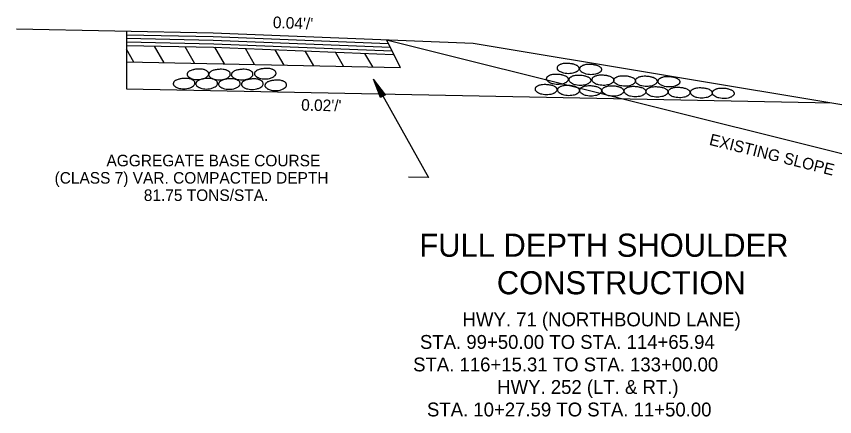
# Model space of a CAD drawing. Extents: x 634177 to 635904, y 289936 to 290970.
# Drawn here: x 635711.28 to 635753.77, y 290762.35 to 290783.15 of the extents above; entities that cross this region are included whole.
import ezdxf

# ---------------------------------------------------------------- set-up
doc = ezdxf.new("R2010")
doc.units = 0
doc.layers.add('Default', color=7, linetype='Continuous')

msp = doc.modelspace()

# ---------------------------------------------------------------- linework, layer by layer
at = {"layer": 'Default'}
for p, q in [((635711.282, 290782.495), (635721.496, 290782.291)), ((635716.996, 290782.375), (635716.996, 290779.379)), ((635716.996, 290782.006), (635721.496, 290781.916)), ((635717, 290782.194), (635721.496, 290782.104)), ((635721.496, 290782.291), (635734.996, 290781.751)), ((635721.496, 290782.104), (635730.592, 290781.74)), ((635716.996, 290781.816), (635721.531, 290781.72)), ((635716.996, 290781.63), (635721.511, 290781.541)), ((635718.959, 290780.739), (635718.462, 290781.601)), ((635720.536, 290780.707), (635720.039, 290781.57)), ((635721.496, 290781.916), (635730.687, 290781.548)), ((635721.531, 290781.72), (635730.787, 290781.35)), ((635730.496, 290781.931), (635731.215, 290780.493)), ((635730.496, 290781.931), (635762.121, 290774.026)), ((635734.996, 290781.751), (635784.496, 290773.501)), ((635717.382, 290780.771), (635716.996, 290781.439)), ((635721.511, 290781.541), (635730.854, 290781.167)), ((635722.087, 290780.676), (635721.589, 290781.539)), ((635723.654, 290780.645), (635723.175, 290781.474)), ((635725.185, 290780.614), (635724.724, 290781.412)), ((635726.726, 290780.583), (635726.283, 290781.35)), ((635728.274, 290780.552), (635727.85, 290781.287)), ((635729.787, 290780.522), (635729.38, 290781.226)), ((635716.996, 290780.778), (635731.215, 290780.493)), ((635730.459, 290779.075), (635729.827, 290779.88)), ((635730.195, 290778.925), (635729.827, 290779.88)), ((635730.437, 290779.062), (635729.911, 290779.733)), ((635730.217, 290778.937), (635729.911, 290779.733)), ((635730.24, 290778.95), (635729.997, 290779.582)), ((635730.415, 290779.05), (635729.997, 290779.582)), ((635716.996, 290779.379), (635753.626, 290778.646)), ((635730.393, 290779.037), (635730.08, 290779.435)), ((635730.262, 290778.963), (635730.08, 290779.435)), ((635730.284, 290778.975), (635730.165, 290779.286)), ((635730.37, 290779.024), (635730.165, 290779.286)), ((635730.459, 290779.075), (635730.195, 290778.925)), ((635730.306, 290778.988), (635730.248, 290779.139)), ((635730.348, 290779.012), (635730.248, 290779.139))]:
    msp.add_line(p, q, dxfattribs=at)
msp.add_lwpolyline([(635729.827, 290779.88), (635732.687, 290774.784), (635731.642, 290774.787)], dxfattribs=at)
for points in [[(635740.458, 290780.546), (635740.48, 290780.507), (635740.492, 290780.474), (635740.501, 290780.429), (635740.494, 290780.402), (635740.471, 290780.359), (635740.444, 290780.325), (635740.397, 290780.289), (635740.366, 290780.262), (635740.339, 290780.253), (635740.28, 290780.224), (635740.179, 290780.197), (635740.026, 290780.172), (635739.871, 290780.174), (635739.706, 290780.201), (635739.542, 290780.26), (635739.448, 290780.325), (635739.389, 290780.395), (635739.376, 290780.451), (635739.378, 290780.503), (635739.396, 290780.557), (635739.416, 290780.582), (635739.448, 290780.609), (635739.488, 290780.631), (635739.535, 290780.66), (635739.574, 290780.674), (635739.648, 290780.699), (635739.754, 290780.714), (635739.898, 290780.719), (635740.003, 290780.71), (635740.111, 290780.696), (635740.168, 290780.683), (635740.244, 290780.665), (635740.332, 290780.631), (635740.381, 290780.604), (635740.442, 290780.559), (635740.469, 290780.534)], [(635720.186, 290780.237), (635720.164, 290780.199), (635720.152, 290780.165), (635720.143, 290780.12), (635720.15, 290780.093), (635720.173, 290780.05), (635720.2, 290780.017), (635720.247, 290779.981), (635720.278, 290779.954), (635720.305, 290779.945), (635720.364, 290779.915), (635720.465, 290779.888), (635720.618, 290779.864), (635720.773, 290779.866), (635720.938, 290779.893), (635721.102, 290779.951), (635721.196, 290780.017), (635721.255, 290780.086), (635721.268, 290780.143), (635721.266, 290780.194), (635721.248, 290780.248), (635721.228, 290780.273), (635721.196, 290780.3), (635721.156, 290780.323), (635721.109, 290780.352), (635721.07, 290780.365), (635720.996, 290780.39), (635720.89, 290780.406), (635720.746, 290780.41), (635720.641, 290780.401), (635720.533, 290780.388), (635720.476, 290780.374), (635720.4, 290780.356), (635720.312, 290780.323), (635720.263, 290780.296), (635720.202, 290780.251), (635720.175, 290780.226)], [(635721.309, 290780.224), (635721.287, 290780.185), (635721.276, 290780.152), (635721.267, 290780.107), (635721.273, 290780.08), (635721.296, 290780.037), (635721.323, 290780.003), (635721.37, 290779.967), (635721.402, 290779.94), (635721.429, 290779.931), (635721.487, 290779.902), (635721.588, 290779.875), (635721.741, 290779.85), (635721.897, 290779.852), (635722.061, 290779.879), (635722.225, 290779.938), (635722.32, 290780.003), (635722.378, 290780.073), (635722.392, 290780.129), (635722.389, 290780.181), (635722.371, 290780.235), (635722.351, 290780.26), (635722.32, 290780.287), (635722.279, 290780.309), (635722.232, 290780.338), (635722.194, 290780.352), (635722.119, 290780.377), (635722.014, 290780.392), (635721.87, 290780.397), (635721.764, 290780.388), (635721.656, 290780.374), (635721.6, 290780.361), (635721.523, 290780.343), (635721.435, 290780.309), (635721.386, 290780.282), (635721.325, 290780.237), (635721.298, 290780.212)], [(635722.486, 290780.223), (635722.464, 290780.185), (635722.453, 290780.151), (635722.444, 290780.106), (635722.45, 290780.079), (635722.473, 290780.037), (635722.5, 290780.003), (635722.547, 290779.967), (635722.579, 290779.94), (635722.606, 290779.931), (635722.664, 290779.902), (635722.765, 290779.875), (635722.918, 290779.85), (635723.074, 290779.852), (635723.238, 290779.879), (635723.402, 290779.938), (635723.497, 290780.003), (635723.555, 290780.073), (635723.569, 290780.129), (635723.566, 290780.181), (635723.548, 290780.235), (635723.528, 290780.259), (635723.497, 290780.286), (635723.456, 290780.309), (635723.409, 290780.338), (635723.371, 290780.352), (635723.296, 290780.376), (635723.191, 290780.392), (635723.047, 290780.397), (635722.941, 290780.388), (635722.833, 290780.374), (635722.777, 290780.361), (635722.7, 290780.343), (635722.612, 290780.309), (635722.563, 290780.282), (635722.502, 290780.237), (635722.475, 290780.212)], [(635723.683, 290780.271), (635723.661, 290780.232), (635723.649, 290780.199), (635723.64, 290780.154), (635723.647, 290780.127), (635723.67, 290780.084), (635723.697, 290780.05), (635723.744, 290780.014), (635723.775, 290779.987), (635723.802, 290779.978), (635723.861, 290779.949), (635723.962, 290779.922), (635724.115, 290779.897), (635724.27, 290779.899), (635724.435, 290779.926), (635724.599, 290779.985), (635724.693, 290780.05), (635724.752, 290780.12), (635724.765, 290780.176), (635724.763, 290780.228), (635724.745, 290780.282), (635724.725, 290780.307), (635724.693, 290780.334), (635724.653, 290780.356), (635724.606, 290780.385), (635724.567, 290780.399), (635724.493, 290780.424), (635724.387, 290780.439), (635724.243, 290780.444), (635724.138, 290780.435), (635724.03, 290780.421), (635723.973, 290780.408), (635723.897, 290780.39), (635723.809, 290780.356), (635723.76, 290780.329), (635723.699, 290780.284), (635723.672, 290780.259)], [(635741.629, 290780.493), (635741.651, 290780.455), (635741.662, 290780.421), (635741.671, 290780.376), (635741.665, 290780.349), (635741.642, 290780.306), (635741.615, 290780.273), (635741.568, 290780.237), (635741.536, 290780.21), (635741.509, 290780.201), (635741.451, 290780.171), (635741.35, 290780.144), (635741.197, 290780.12), (635741.041, 290780.122), (635740.877, 290780.149), (635740.713, 290780.207), (635740.618, 290780.273), (635740.56, 290780.342), (635740.546, 290780.399), (635740.549, 290780.45), (635740.567, 290780.504), (635740.587, 290780.529), (635740.618, 290780.556), (635740.659, 290780.579), (635740.706, 290780.608), (635740.744, 290780.621), (635740.819, 290780.646), (635740.924, 290780.662), (635741.068, 290780.666), (635741.174, 290780.657), (635741.282, 290780.644), (635741.338, 290780.63), (635741.415, 290780.612), (635741.503, 290780.579), (635741.552, 290780.552), (635741.613, 290780.507), (635741.64, 290780.482)], [(635719.469, 290779.753), (635719.446, 290779.715), (635719.435, 290779.681), (635719.426, 290779.636), (635719.433, 290779.609), (635719.455, 290779.567), (635719.482, 290779.533), (635719.529, 290779.497), (635719.561, 290779.47), (635719.588, 290779.461), (635719.646, 290779.432), (635719.748, 290779.405), (635719.901, 290779.38), (635720.056, 290779.382), (635720.22, 290779.409), (635720.384, 290779.468), (635720.479, 290779.533), (635720.537, 290779.603), (635720.551, 290779.659), (635720.549, 290779.711), (635720.531, 290779.765), (635720.51, 290779.789), (635720.479, 290779.816), (635720.438, 290779.839), (635720.391, 290779.868), (635720.353, 290779.882), (635720.279, 290779.906), (635720.173, 290779.922), (635720.029, 290779.927), (635719.923, 290779.918), (635719.815, 290779.904), (635719.759, 290779.891), (635719.682, 290779.873), (635719.595, 290779.839), (635719.545, 290779.812), (635719.484, 290779.767), (635719.457, 290779.742)], [(635720.642, 290779.749), (635720.62, 290779.711), (635720.608, 290779.677), (635720.599, 290779.632), (635720.606, 290779.605), (635720.629, 290779.562), (635720.656, 290779.528), (635720.703, 290779.492), (635720.734, 290779.465), (635720.761, 290779.456), (635720.82, 290779.427), (635720.921, 290779.4), (635721.074, 290779.375), (635721.229, 290779.378), (635721.394, 290779.405), (635721.558, 290779.463), (635721.652, 290779.528), (635721.711, 290779.598), (635721.724, 290779.654), (635721.722, 290779.706), (635721.704, 290779.76), (635721.684, 290779.785), (635721.652, 290779.812), (635721.612, 290779.834), (635721.565, 290779.864), (635721.526, 290779.877), (635721.452, 290779.902), (635721.346, 290779.918), (635721.202, 290779.922), (635721.097, 290779.913), (635720.989, 290779.9), (635720.932, 290779.886), (635720.856, 290779.868), (635720.768, 290779.834), (635720.719, 290779.807), (635720.658, 290779.762), (635720.631, 290779.738)], [(635721.819, 290779.732), (635721.797, 290779.694), (635721.785, 290779.66), (635721.776, 290779.615), (635721.783, 290779.588), (635721.806, 290779.545), (635721.833, 290779.512), (635721.88, 290779.476), (635721.911, 290779.449), (635721.938, 290779.44), (635721.997, 290779.41), (635722.098, 290779.383), (635722.251, 290779.359), (635722.406, 290779.361), (635722.571, 290779.388), (635722.735, 290779.446), (635722.829, 290779.512), (635722.888, 290779.581), (635722.901, 290779.638), (635722.899, 290779.689), (635722.881, 290779.743), (635722.861, 290779.768), (635722.829, 290779.795), (635722.789, 290779.818), (635722.742, 290779.847), (635722.703, 290779.86), (635722.629, 290779.885), (635722.523, 290779.901), (635722.379, 290779.905), (635722.274, 290779.896), (635722.166, 290779.883), (635722.109, 290779.869), (635722.033, 290779.851), (635721.945, 290779.818), (635721.896, 290779.791), (635721.835, 290779.746), (635721.808, 290779.721)], [(635723.014, 290779.724), (635722.991, 290779.686), (635722.98, 290779.652), (635722.971, 290779.607), (635722.978, 290779.58), (635723, 290779.538), (635723.027, 290779.504), (635723.074, 290779.468), (635723.106, 290779.441), (635723.133, 290779.432), (635723.191, 290779.403), (635723.293, 290779.376), (635723.446, 290779.351), (635723.601, 290779.353), (635723.765, 290779.38), (635723.929, 290779.439), (635724.024, 290779.504), (635724.082, 290779.574), (635724.096, 290779.63), (635724.094, 290779.682), (635724.076, 290779.736), (635724.055, 290779.76), (635724.024, 290779.787), (635723.983, 290779.81), (635723.936, 290779.839), (635723.898, 290779.853), (635723.824, 290779.877), (635723.718, 290779.893), (635723.574, 290779.898), (635723.468, 290779.889), (635723.36, 290779.875), (635723.304, 290779.862), (635723.227, 290779.844), (635723.14, 290779.81), (635723.09, 290779.783), (635723.029, 290779.738), (635723.002, 290779.713)], [(635739.9, 290779.979), (635739.923, 290779.941), (635739.934, 290779.907), (635739.943, 290779.862), (635739.936, 290779.835), (635739.914, 290779.792), (635739.887, 290779.758), (635739.84, 290779.722), (635739.808, 290779.695), (635739.781, 290779.686), (635739.723, 290779.657), (635739.621, 290779.63), (635739.468, 290779.605), (635739.313, 290779.608), (635739.149, 290779.635), (635738.985, 290779.693), (635738.89, 290779.758), (635738.832, 290779.828), (635738.818, 290779.884), (635738.82, 290779.936), (635738.838, 290779.99), (635738.859, 290780.015), (635738.89, 290780.042), (635738.931, 290780.064), (635738.978, 290780.094), (635739.016, 290780.107), (635739.09, 290780.132), (635739.196, 290780.148), (635739.34, 290780.152), (635739.446, 290780.143), (635739.554, 290780.13), (635739.61, 290780.116), (635739.687, 290780.098), (635739.774, 290780.064), (635739.824, 290780.037), (635739.885, 290779.992), (635739.912, 290779.968)], [(635741.071, 290779.926), (635741.094, 290779.888), (635741.105, 290779.854), (635741.114, 290779.809), (635741.107, 290779.782), (635741.085, 290779.74), (635741.058, 290779.706), (635741.01, 290779.67), (635740.979, 290779.643), (635740.952, 290779.634), (635740.893, 290779.605), (635740.792, 290779.578), (635740.639, 290779.553), (635740.484, 290779.555), (635740.32, 290779.582), (635740.155, 290779.641), (635740.061, 290779.706), (635740.002, 290779.776), (635739.989, 290779.832), (635739.991, 290779.884), (635740.009, 290779.938), (635740.029, 290779.962), (635740.061, 290779.989), (635740.101, 290780.012), (635740.149, 290780.041), (635740.187, 290780.055), (635740.261, 290780.079), (635740.367, 290780.095), (635740.511, 290780.1), (635740.617, 290780.091), (635740.725, 290780.077), (635740.781, 290780.064), (635740.857, 290780.046), (635740.945, 290780.012), (635740.995, 290779.985), (635741.055, 290779.94), (635741.082, 290779.915)], [(635742.266, 290779.936), (635742.289, 290779.897), (635742.3, 290779.864), (635742.309, 290779.819), (635742.302, 290779.792), (635742.28, 290779.749), (635742.253, 290779.715), (635742.205, 290779.679), (635742.174, 290779.652), (635742.147, 290779.643), (635742.088, 290779.614), (635741.987, 290779.587), (635741.834, 290779.562), (635741.679, 290779.564), (635741.515, 290779.591), (635741.35, 290779.65), (635741.256, 290779.715), (635741.197, 290779.785), (635741.184, 290779.841), (635741.186, 290779.893), (635741.204, 290779.947), (635741.224, 290779.972), (635741.256, 290779.999), (635741.296, 290780.021), (635741.344, 290780.05), (635741.382, 290780.064), (635741.456, 290780.089), (635741.562, 290780.104), (635741.706, 290780.109), (635741.812, 290780.1), (635741.92, 290780.086), (635741.976, 290780.073), (635742.052, 290780.055), (635742.14, 290780.021), (635742.19, 290779.994), (635742.25, 290779.949), (635742.277, 290779.924)], [(635743.392, 290779.891), (635743.414, 290779.852), (635743.426, 290779.819), (635743.435, 290779.774), (635743.428, 290779.747), (635743.405, 290779.704), (635743.378, 290779.67), (635743.331, 290779.634), (635743.3, 290779.607), (635743.273, 290779.598), (635743.214, 290779.569), (635743.113, 290779.542), (635742.96, 290779.517), (635742.805, 290779.519), (635742.64, 290779.546), (635742.476, 290779.605), (635742.382, 290779.67), (635742.323, 290779.74), (635742.31, 290779.796), (635742.312, 290779.848), (635742.33, 290779.902), (635742.35, 290779.927), (635742.382, 290779.954), (635742.422, 290779.976), (635742.469, 290780.005), (635742.508, 290780.019), (635742.582, 290780.044), (635742.688, 290780.059), (635742.832, 290780.064), (635742.937, 290780.055), (635743.045, 290780.041), (635743.102, 290780.028), (635743.178, 290780.01), (635743.266, 290779.976), (635743.315, 290779.949), (635743.376, 290779.904), (635743.403, 290779.879)], [(635744.518, 290779.876), (635744.54, 290779.837), (635744.551, 290779.804), (635744.56, 290779.759), (635744.554, 290779.732), (635744.531, 290779.689), (635744.504, 290779.655), (635744.457, 290779.619), (635744.425, 290779.592), (635744.398, 290779.583), (635744.34, 290779.554), (635744.239, 290779.527), (635744.086, 290779.502), (635743.93, 290779.504), (635743.766, 290779.531), (635743.602, 290779.59), (635743.507, 290779.655), (635743.449, 290779.725), (635743.435, 290779.781), (635743.438, 290779.833), (635743.456, 290779.887), (635743.476, 290779.912), (635743.507, 290779.939), (635743.548, 290779.961), (635743.595, 290779.99), (635743.633, 290780.004), (635743.708, 290780.029), (635743.813, 290780.044), (635743.957, 290780.049), (635744.063, 290780.04), (635744.171, 290780.026), (635744.227, 290780.013), (635744.304, 290779.995), (635744.392, 290779.961), (635744.441, 290779.934), (635744.502, 290779.889), (635744.529, 290779.864)], [(635745.696, 290779.853), (635745.718, 290779.815), (635745.73, 290779.781), (635745.739, 290779.736), (635745.732, 290779.709), (635745.709, 290779.666), (635745.682, 290779.633), (635745.635, 290779.597), (635745.604, 290779.57), (635745.577, 290779.561), (635745.518, 290779.531), (635745.417, 290779.504), (635745.264, 290779.48), (635745.109, 290779.482), (635744.944, 290779.509), (635744.78, 290779.567), (635744.686, 290779.633), (635744.627, 290779.702), (635744.614, 290779.759), (635744.616, 290779.81), (635744.634, 290779.864), (635744.654, 290779.889), (635744.686, 290779.916), (635744.726, 290779.939), (635744.773, 290779.968), (635744.812, 290779.981), (635744.886, 290780.006), (635744.992, 290780.022), (635745.136, 290780.026), (635745.241, 290780.017), (635745.349, 290780.004), (635745.406, 290779.99), (635745.482, 290779.972), (635745.57, 290779.939), (635745.619, 290779.912), (635745.68, 290779.867), (635745.707, 290779.842)], [(635724.227, 290779.664), (635724.205, 290779.626), (635724.194, 290779.592), (635724.185, 290779.547), (635724.191, 290779.52), (635724.214, 290779.478), (635724.241, 290779.444), (635724.288, 290779.408), (635724.32, 290779.381), (635724.347, 290779.372), (635724.405, 290779.343), (635724.506, 290779.316), (635724.659, 290779.291), (635724.815, 290779.293), (635724.979, 290779.32), (635725.143, 290779.379), (635725.238, 290779.444), (635725.296, 290779.514), (635725.31, 290779.57), (635725.307, 290779.622), (635725.289, 290779.676), (635725.269, 290779.7), (635725.238, 290779.727), (635725.197, 290779.75), (635725.15, 290779.779), (635725.112, 290779.793), (635725.037, 290779.817), (635724.932, 290779.833), (635724.788, 290779.838), (635724.682, 290779.829), (635724.574, 290779.815), (635724.518, 290779.802), (635724.441, 290779.784), (635724.353, 290779.75), (635724.304, 290779.723), (635724.243, 290779.678), (635724.216, 290779.653)], [(635739.315, 290779.445), (635739.338, 290779.407), (635739.349, 290779.373), (635739.358, 290779.328), (635739.351, 290779.301), (635739.329, 290779.258), (635739.302, 290779.225), (635739.255, 290779.189), (635739.223, 290779.162), (635739.196, 290779.153), (635739.138, 290779.123), (635739.036, 290779.096), (635738.883, 290779.072), (635738.728, 290779.074), (635738.564, 290779.101), (635738.4, 290779.159), (635738.305, 290779.225), (635738.247, 290779.294), (635738.233, 290779.351), (635738.235, 290779.402), (635738.253, 290779.456), (635738.274, 290779.481), (635738.305, 290779.508), (635738.346, 290779.531), (635738.393, 290779.56), (635738.431, 290779.573), (635738.505, 290779.598), (635738.611, 290779.614), (635738.755, 290779.618), (635738.861, 290779.609), (635738.969, 290779.596), (635739.025, 290779.582), (635739.102, 290779.564), (635739.189, 290779.531), (635739.239, 290779.504), (635739.3, 290779.459), (635739.327, 290779.434)], [(635740.479, 290779.4), (635740.501, 290779.362), (635740.512, 290779.328), (635740.521, 290779.283), (635740.515, 290779.256), (635740.492, 290779.213), (635740.465, 290779.18), (635740.418, 290779.144), (635740.386, 290779.117), (635740.359, 290779.108), (635740.301, 290779.078), (635740.2, 290779.051), (635740.047, 290779.027), (635739.891, 290779.029), (635739.727, 290779.056), (635739.563, 290779.114), (635739.468, 290779.18), (635739.41, 290779.249), (635739.396, 290779.306), (635739.399, 290779.357), (635739.417, 290779.411), (635739.437, 290779.436), (635739.468, 290779.463), (635739.509, 290779.486), (635739.556, 290779.515), (635739.594, 290779.528), (635739.669, 290779.553), (635739.774, 290779.569), (635739.918, 290779.573), (635740.024, 290779.564), (635740.132, 290779.551), (635740.188, 290779.537), (635740.265, 290779.519), (635740.353, 290779.486), (635740.402, 290779.459), (635740.463, 290779.414), (635740.49, 290779.389)], [(635741.627, 290779.378), (635741.649, 290779.339), (635741.661, 290779.306), (635741.67, 290779.261), (635741.663, 290779.234), (635741.64, 290779.191), (635741.613, 290779.157), (635741.566, 290779.121), (635741.535, 290779.094), (635741.508, 290779.085), (635741.449, 290779.056), (635741.348, 290779.029), (635741.195, 290779.004), (635741.04, 290779.006), (635740.875, 290779.033), (635740.711, 290779.092), (635740.617, 290779.157), (635740.558, 290779.227), (635740.545, 290779.283), (635740.547, 290779.335), (635740.565, 290779.389), (635740.585, 290779.414), (635740.617, 290779.441), (635740.657, 290779.463), (635740.704, 290779.492), (635740.743, 290779.506), (635740.817, 290779.531), (635740.923, 290779.546), (635741.067, 290779.551), (635741.172, 290779.542), (635741.28, 290779.528), (635741.337, 290779.515), (635741.413, 290779.497), (635741.501, 290779.463), (635741.55, 290779.436), (635741.611, 290779.391), (635741.638, 290779.366)], [(635742.783, 290779.37), (635742.805, 290779.332), (635742.816, 290779.298), (635742.825, 290779.253), (635742.819, 290779.226), (635742.796, 290779.183), (635742.769, 290779.15), (635742.722, 290779.114), (635742.69, 290779.087), (635742.663, 290779.078), (635742.605, 290779.048), (635742.504, 290779.021), (635742.351, 290778.997), (635742.195, 290778.999), (635742.031, 290779.026), (635741.867, 290779.084), (635741.772, 290779.15), (635741.714, 290779.219), (635741.7, 290779.276), (635741.703, 290779.327), (635741.721, 290779.381), (635741.741, 290779.406), (635741.772, 290779.433), (635741.813, 290779.456), (635741.86, 290779.485), (635741.898, 290779.498), (635741.973, 290779.523), (635742.078, 290779.539), (635742.222, 290779.543), (635742.328, 290779.534), (635742.436, 290779.521), (635742.492, 290779.507), (635742.569, 290779.489), (635742.657, 290779.456), (635742.706, 290779.429), (635742.767, 290779.384), (635742.794, 290779.359)], [(635743.931, 290779.34), (635743.953, 290779.302), (635743.965, 290779.268), (635743.974, 290779.223), (635743.967, 290779.196), (635743.944, 290779.153), (635743.917, 290779.12), (635743.87, 290779.084), (635743.839, 290779.057), (635743.812, 290779.048), (635743.753, 290779.018), (635743.652, 290778.991), (635743.499, 290778.967), (635743.344, 290778.969), (635743.179, 290778.996), (635743.015, 290779.054), (635742.921, 290779.12), (635742.862, 290779.189), (635742.849, 290779.246), (635742.851, 290779.297), (635742.869, 290779.351), (635742.889, 290779.376), (635742.921, 290779.403), (635742.961, 290779.426), (635743.008, 290779.455), (635743.047, 290779.468), (635743.121, 290779.493), (635743.227, 290779.509), (635743.371, 290779.513), (635743.476, 290779.504), (635743.584, 290779.491), (635743.641, 290779.477), (635743.717, 290779.459), (635743.805, 290779.426), (635743.854, 290779.399), (635743.915, 290779.354), (635743.942, 290779.329)], [(635745.072, 290779.325), (635745.094, 290779.287), (635745.105, 290779.253), (635745.114, 290779.208), (635745.108, 290779.181), (635745.085, 290779.138), (635745.058, 290779.105), (635745.011, 290779.069), (635744.979, 290779.042), (635744.952, 290779.033), (635744.894, 290779.003), (635744.793, 290778.976), (635744.64, 290778.952), (635744.484, 290778.954), (635744.32, 290778.981), (635744.156, 290779.039), (635744.061, 290779.105), (635744.003, 290779.174), (635743.989, 290779.231), (635743.992, 290779.282), (635744.01, 290779.336), (635744.03, 290779.361), (635744.061, 290779.388), (635744.102, 290779.411), (635744.149, 290779.44), (635744.187, 290779.453), (635744.262, 290779.478), (635744.367, 290779.494), (635744.511, 290779.498), (635744.617, 290779.489), (635744.725, 290779.476), (635744.781, 290779.462), (635744.858, 290779.444), (635744.946, 290779.411), (635744.995, 290779.384), (635745.056, 290779.339), (635745.083, 290779.314)], [(635746.22, 290779.295), (635746.242, 290779.257), (635746.254, 290779.223), (635746.263, 290779.178), (635746.256, 290779.151), (635746.233, 290779.108), (635746.206, 290779.074), (635746.159, 290779.038), (635746.128, 290779.011), (635746.101, 290779.002), (635746.042, 290778.973), (635745.941, 290778.946), (635745.788, 290778.921), (635745.633, 290778.924), (635745.468, 290778.951), (635745.304, 290779.009), (635745.21, 290779.074), (635745.151, 290779.144), (635745.138, 290779.2), (635745.14, 290779.252), (635745.158, 290779.306), (635745.178, 290779.331), (635745.21, 290779.358), (635745.25, 290779.38), (635745.297, 290779.41), (635745.336, 290779.423), (635745.41, 290779.448), (635745.516, 290779.464), (635745.66, 290779.468), (635745.765, 290779.459), (635745.873, 290779.446), (635745.93, 290779.432), (635746.006, 290779.414), (635746.094, 290779.38), (635746.143, 290779.353), (635746.204, 290779.308), (635746.231, 290779.284)], [(635747.376, 290779.272), (635747.398, 290779.234), (635747.409, 290779.2), (635747.418, 290779.155), (635747.412, 290779.128), (635747.389, 290779.086), (635747.362, 290779.052), (635747.315, 290779.016), (635747.283, 290778.989), (635747.256, 290778.98), (635747.198, 290778.951), (635747.097, 290778.924), (635746.944, 290778.899), (635746.788, 290778.901), (635746.624, 290778.928), (635746.46, 290778.987), (635746.365, 290779.052), (635746.307, 290779.122), (635746.293, 290779.178), (635746.296, 290779.23), (635746.314, 290779.284), (635746.334, 290779.308), (635746.365, 290779.335), (635746.406, 290779.358), (635746.453, 290779.387), (635746.491, 290779.401), (635746.566, 290779.425), (635746.671, 290779.441), (635746.815, 290779.446), (635746.921, 290779.437), (635747.029, 290779.423), (635747.085, 290779.41), (635747.162, 290779.392), (635747.25, 290779.358), (635747.299, 290779.331), (635747.36, 290779.286), (635747.387, 290779.261)], [(635748.516, 290779.25), (635748.539, 290779.212), (635748.55, 290779.178), (635748.559, 290779.133), (635748.552, 290779.106), (635748.53, 290779.063), (635748.503, 290779.029), (635748.456, 290778.993), (635748.424, 290778.966), (635748.397, 290778.957), (635748.339, 290778.928), (635748.237, 290778.901), (635748.084, 290778.876), (635747.929, 290778.879), (635747.765, 290778.906), (635747.601, 290778.964), (635747.506, 290779.029), (635747.448, 290779.099), (635747.434, 290779.155), (635747.436, 290779.207), (635747.454, 290779.261), (635747.475, 290779.286), (635747.506, 290779.313), (635747.547, 290779.335), (635747.594, 290779.365), (635747.632, 290779.378), (635747.706, 290779.403), (635747.812, 290779.419), (635747.956, 290779.423), (635748.062, 290779.414), (635748.17, 290779.401), (635748.226, 290779.387), (635748.303, 290779.369), (635748.39, 290779.335), (635748.44, 290779.308), (635748.501, 290779.263), (635748.528, 290779.239)]]:
    msp.add_spline(points, degree=3, dxfattribs=at)

# ---------------------------------------------------------------- texts
for s, rotation, p in [("0.04'/'", 357.7094, (635724.591, 290782.543)), ("0.02'/'", 358.854, (635726.067, 290778.25)), ('EXISTING SLOPE', 345.9661, (635747.224, 290776.478))]:
    msp.add_text(s, height=0.6, rotation=rotation, dxfattribs=at).set_placement(p)
for s, height, p in [('AGGREGATE BASE COURSE', 0.6, (635715.962, 290775.357)), ('(CLASS 7) VAR. COMPACTED DEPTH', 0.6, (635713.267, 290774.457)), ('81.75 TONS/STA.', 0.6, (635717.9, 290773.557)), ('FULL DEPTH SHOULDER', 1.2, (635732.206, 290770.659)), ('CONSTRUCTION', 1.2, (635736.231, 290768.709)), ('HWY. 71 (NORTHBOUND LANE)', 0.72, (635734.453, 290767.043)), ('STA. 99+50.00 TO STA. 114+65.94', 0.72, (635732.24, 290765.873)), ('STA. 116+15.31 TO STA. 133+00.00', 0.72, (635731.885, 290764.703)), ('HWY. 252 (LT. & RT.)', 0.72, (635736.253, 290763.533)), ('STA. 10+27.59 TO STA. 11+50.00', 0.72, (635732.605, 290762.363))]:
    msp.add_text(s, height=height, dxfattribs=at).set_placement(p)

doc.saveas('drawing.dxf')
